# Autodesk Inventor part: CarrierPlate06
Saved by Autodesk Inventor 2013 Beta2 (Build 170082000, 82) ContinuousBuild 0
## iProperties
Created: 2008-02
Part Number: CarrierPlate06
Document SubType Name: Modeling
Designer: grh
Density: 1 g/cm^3
Material: Generic
Author: grh
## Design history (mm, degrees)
sketch "Sketch1"
  geometry: L1 (48.514, 0)-(0, 0); L2 (0, 0)-(37.164, 31.184); L3 (8.424, 47.777)-(0, 0); L4 (-24.257, 42.014)-(0, 0); L5 (-45.588, 16.593)-(0, 0); L6 (-45.588, -16.593)-(0, 0); C1 r 53.34 at (0, 0)
  constraints: 12 end point, 5 equal length, 1 centre point, 1 horizontal, 1 other
  dimensions: "BlankDiameter" = 106.68 diameter of C1; "PlanetRadius" = 48.514 distance of L1.start L1.end; "Angle1" = 40 deg angle of L2 L1; "Angle2" = 40 deg angle of L3 L2; "Angle3" = 40 deg angle of L4 L3; "Angle4" = 40 deg angle of L5 L4; "Angle5" = 40 deg angle of L6 L5
extrude "Extrusion1" new body sketch "Sketch1" stored distance "d9" = 13.97; taper "d10" = 0 deg
node "Axis1"
node "Axis2"
node "Axis3"
node "Axis4"
node "Axis5"
node "Axis6"
node "Axis7"
body "Solid1"
